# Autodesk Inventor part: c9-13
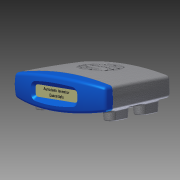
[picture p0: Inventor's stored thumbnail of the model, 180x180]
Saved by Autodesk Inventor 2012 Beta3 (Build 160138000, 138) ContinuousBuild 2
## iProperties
Created: 2010-12
Part Number: c9-13
Material: Default
Document SubType Name: Modeling
Designer: Beta-8540w
Density: 1 g/cm^3
Author: Beta-8540w
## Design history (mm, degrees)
sketch "Sketch1"
  geometry: L1 (-60, -12)-(60, -12); L2 (60, -12)-(60, 12); L3 (60, 12)-(-60, 12); L4 (-60, 12)-(-60, -12); A1 r 350 centre (0, -332.819) between (60, 12) and (-60, 12); A2 r 350 centre (0, 332.819) between (-60, -12) and (60, -12); 3 further points
  constraints: 8 end point, 4 point on circle, 2 centre point, 2 midpoint, 2 parallel, 1 equal radius, 1 horizontal, 1 horizontal alignment, 1 perpendicular, 1 vertical alignment
  dimensions: "d0" = 120 distance of L3.end L2.end; "d1" = 24 distance of L2.end L1.end; "d2" = 350 radius of A1
workplane "Work Plane4"
sketch "Sketch5"
  geometry: L1 (-60, 12)-(-60, -12) reference; L2 (60, -12)-(60, 12) reference; L3 (-58, 10.314)-(-58, -10.314); L4 (58, -10.314)-(58, 10.314); A1 r 350 centre (0, 332.819) between (-60, -12) and (60, -12) reference; A2 r 350 centre (0, -332.819) between (60, 12) and (-60, 12) reference; A3 r 348 centre (0, 332.819) between (-58, -10.314) and (58, -10.314); A4 r 348 centre (0, -332.819) between (58, 10.314) and (-58, 10.314); 1 further point
  constraints: 4 end point, 4 point on circle, 2 centre point, 3 other
  dimensions: "d37" = 2 distance between parallel lines of L2 L4
sketch "Sketch6"
  geometry: L1 (-60, 0)-(60, 0); L2 (60, 0)-(58.843, 22.085); L3 (-60, 0)-(-58.779, 23.307); A1 r 691.758 centre (630.81, -36.204) between (-60, 0) and (-58, -100); A2 r 691.758 centre (-630.81, -36.204) between (58, -100) and (60, 0); 1 further point
  constraints: 6 end point, 4 point on circle, 2 centre point, 2 tangent, 1 horizontal
  dimensions: "d53" = 87 deg angle of L1 L3; "d54" = 87 deg angle of L1 L2 (= d53)
sketch "Sketch7"
  geometry: L1 (17.181, 0)-(12, 0) reference; L2 (15.181, -100)-(10.314, -100) reference; L3 (17.181, 0)-(16.768, 11.838); A1 r 911.322 centre (-893.585, -31.805) between (15.181, -100) and (17.181, 0); 1 further point
  constraints: 2 end point, 2 point on circle, 1 centre point, 1 tangent
  dimensions: "d56" = 88 deg angle of L1 L3
feature "LoftSrf2" sketch "Sketch5", "Sketch6", "Sketch7" dims "d57" = 0, "d58" = 90 deg, "d59" = 0, "d60" = 90 deg, "d61" = 0, "d62" = 90 deg, "d63" = 0, "d64" = 90 deg, "d65" = 0, "d66" = 90 deg
sketch "Sketch2"
  geometry: L1 (-75, -16)-(75, -16); L2 (-75, -60)-(75, -60); A1 r 183.781 centre (0, -183.781) between (75, -16) and (-75, -16); 2 further points
  constraints: 4 end point, 3 point on circle, 1 centre point, 1 coincident, 1 horizontal, 1 parallel
  dimensions: "d5" = 16 distance from line of point (0, 0) L1; "d7" = 60 distance from line of point (0, 0) L2; "d55" = 150 distance of L1.start L1.end
feature "RevolutionSrf1" sketch "Sketch2" dims angle "d8" = 40 deg
patch "Boundary Patch1" dims "d13" = 0, "d67" = 0, "d68" = 0, "d69" = 0, "d70" = 0
workplane "Work Plane1"
sketch "Sketch3"
  geometry: L1 (52, -85)-(52, -73); L2 (38, -73)-(38, -85); A1 r 7 centre (45, -73) between (52, -73) and (38, -73); A2 r 7 centre (45, -85) between (38, -85) and (52, -85); 1 further point
  constraints: 4 end point, 4 point on circle, 4 tangent, 2 centre point, 1 parallel, 1 vertical
  dimensions: "d15" = 12 distance of L1.start L1.end; "d16" = 7 radius of A1; "d50" = 45 horizontal distance of A1.centre point (0, 0); "d51" = 85 vertical distance of point (0, 0) A2.centre
extrude_surface "ExtrusionSrf2" sketch "Sketch3" dims "d19" = 14, "d20" = 5 deg
pattern_linear "Rectangular Pattern1" dims "d23" = 90
workplane "Work Plane2"
feature "Sculpt1"
sketch "Sketch4"
  geometry: L1 (-24.5, 6)-(24.5, 6); L2 (27.5, 3)-(27.5, -3); L3 (24.5, -6)-(-24.5, -6); L4 (-27.5, -3)-(-27.5, 3); A1 r 3 centre (-24.5, 3) between (-24.5, 6) and (-27.5, 3); A2 r 3 centre (24.5, 3) between (27.5, 3) and (24.5, 6); A3 r 3 centre (24.5, -3) between (24.5, -6) and (27.5, -3); A4 r 3 centre (-24.5, -3) between (-27.5, -3) and (-24.5, -6); 6 further points
  constraints: 8 end point, 8 point on circle, 8 tangent, 6 point on line, 4 centre point, 3 equal radius, 2 midpoint, 2 parallel, 1 horizontal, 1 horizontal alignment, 1 perpendicular, 1 vertical alignment
  dimensions: "d28" = 55 distance of point (27.5, -6) point (-27.5, -6); "d29" = 12 distance of point (27.5, 6) point (27.5, -6); "d30" = 3 radius of A1
extrude_surface "ExtrusionSrf6" sketch "Sketch4" dims "d31" = 14, "d32" = 45 deg
patch "Boundary Patch2" dims "d33" = 0, "d34" = 0
fillet "Fillet1" dims "d79" = 4, "d80" = 3, "d81" = 1
feature "Sculpt2"
node "Splitting Plane 1"
shell "Shell1" dims "d83" = 2
split "Split1"
  body "Solid1"
feature "Lip1" dims "d188" = 1, "d189" = 1, "d190" = 0, "d191" = 0, "d192" = 0, "d193" = 0
feature "Lip2" dims "d194" = 1, "d195" = 1, "d196" = 0, "d197" = 0, "d198" = 0, "d199" = 0.5
split "Split3"
  node "Back"
sketch "Sketch9"
  geometry: L1 (50.167, -73)-(50.167, -85) reference; L2 (39.833, -85)-(39.833, -73) reference; L3 (45, -73)-(45, -85); L4 (45, -85)-(39.833, -85); A1 r 5.167 centre (45, -73) between (50.167, -73) and (39.833, -73) reference; A2 r 5.167 centre (45, -85) between (39.833, -85) and (50.167, -85) reference; 5 further points
  constraints: 4 end point, 1 horizontal, 1 midpoint, 1 parallel, 1 perpendicular, 1 vertical, 3 other
  dimensions: "d86" = 90 distance of point (45, -79) point (-45, -79); "d89" = 40 distance of point (45, -79) point (45, -39)
  node "Projected Loop1"
feature "Boss1" dims "d92" = 0, "d93" = 0, "d94" = 7, "d95" = 2, "d96" = 0.5, "d97" = 6, "d98" = 1.25, "d99" = 3.5, "d100" = 2.5 deg, "d101" = 2.5 deg, "d102" = 2.5 deg, "d103" = 2.5 deg, "d104" = 90 deg, "d107" = 2, "d108" = 2, "d109" = 10, "d110" = 0, "d111" = 10 deg, "d112" = 2.5 deg, "d113" = 0, "d114" = 0, "d115" = 0, "d116" = 360 deg
feature "Boss2" dims "d117" = 3, "d118" = 0, "d119" = 6, "d120" = 3, "d121" = 9.5, "d122" = 2 deg, "d123" = 1 deg, "d126" = 2, "d127" = 2, "d128" = 10, "d129" = 0, "d130" = 10 deg, "d131" = 2.5 deg, "d132" = 0, "d133" = 0, "d134" = 0, "d135" = 360 deg
workplane "Work Plane6"
sketch "Sketch10"
  geometry: L1 (24, -85)-(-24, -85); L2 (-30, -79)-(-30, -51); L3 (-24, -45)-(24, -45); L4 (30, -51)-(30, -79); L5 (54.344, -100)-(-54.344, -100) reference; A1 r 6 centre (-24, -51) between (-24, -45) and (-30, -51); A2 r 6 centre (24, -51) between (30, -51) and (24, -45); A3 r 6 centre (24, -79) between (24, -85) and (30, -79); A4 r 6 centre (-24, -79) between (-30, -79) and (-24, -85); 5 further points
  constraints: 8 end point, 8 point on circle, 8 tangent, 6 point on line, 4 centre point, 3 equal radius, 2 parallel, 1 horizontal, 1 midpoint, 1 perpendicular, 1 vertical alignment
  dimensions: "d137" = 60 distance of point (-30, -45) point (30, -45); "d138" = 40 distance of point (-30, -85) point (-30, -45); "d139" = 15 distance between parallel lines of L5 L1; "d141" = 6 radius of A2
feature "Rest1" sketch "Sketch10" dims "d142" = 5, "d143" = 0, "d144" = 0, "d145" = 0, "d146" = 2 deg, "d147" = 2 deg, "d148" = 2
feature "Rule Fillet1" dims "d149" = 2, "d150" = 1
workplane "Work Plane7"
sketch "Sketch11" dims "d154" = 16, "d155" = 8, "d161" = 10, "d168" = 10
  geometry: L1 (-13, -39.858)-(-13, -90.142); L2 (-25.187, -85)-(29.449, -85); L3 (0, -39.858)-(0, -90.142); L4 (13, -39.858)-(13, -90.142); L5 (-25.187, -77)-(29.449, -77); L6 (-25.187, -69)-(29.449, -69); L7 (-25.187, -61)-(29.449, -61); L8 (-25.187, -53)-(29.449, -53); L9 (-25.187, -45)-(29.449, -45); C1 r 22.5 at (0, -65); 3 further points; 1 other entity
  constraints: 18 end point, 2 coincident, 2 vertical, 1 centre point, 1 horizontal, 1 midpoint, 1 perpendicular, 1 vertical alignment, 23 other
  dimensions: "d152" = 45 diameter of C1; "d153" = 65 distance of point (0, 0) C1.centre; "d158" = 13 distance of L1.start L3.start; "d165" = 8 distance of L2.start L5.start; "d170" = 4 distance from line of L7 point (0, -65)
feature "Grill1" sketch "Sketch11" dims "d173" = 2, "d174" = 0, "d175" = 1, "d176" = 2, "d177" = 0, "d178" = 1, "d179" = 0.5, "d180" = 0, "d181" = 2, "d182" = 1, "d183" = 2 deg, "d184" = 0, "d185" = 88.84492
sketch "Sketch12"
  geometry: L1 (-12.481, -61.203)-(12.401, -61.203); L2 (12.401, -61.203)-(12.401, -68.714); L3 (12.401, -68.714)-(-12.481, -68.714); L4 (-12.481, -68.714)-(-12.481, -61.203); 1 further point
  constraints: 2 other
emboss "Emboss1" sketch "Sketch12" dims "d186" = 0.5, "d187" = 0
sketch "Sketch13"
  geometry: L1 (0, 15.66)-(0, -14.781); 6 further points
  constraints: 2 end point, 1 coincident, 1 point on line, 1 vertical, 4 other
feature "Snap Fit1" sketch "Sketch13" dims "d200" = 4, "d201" = 2.5, "d202" = 1, "d203" = 0.9, "d204" = 10.2, "d205" = 10, "d206" = 1, "d207" = 1, "d208" = 50 deg, "d209" = 50 deg
fillet "Fillet2" dims "d213" = 2
workplane "Work Plane8"
sketch "Sketch14"
  geometry: L1 (-8.644, -6.828)-(57.644, -6.828); L2 (6.5, 3.689)-(6.5, -17.346); L3 (24.5, 3.689)-(24.5, -17.346); L4 (42.5, 3.689)-(42.5, -17.346); 2 further points
  constraints: 8 end point, 4 parallel, 2 horizontal alignment, 2 midpoint, 1 coincident, 1 horizontal, 1 perpendicular
  dimensions: "d211" = 18 distance between parallel lines of L3 L2; "d212" = 18 distance between parallel lines of L4 L3 (= d211)
feature "Rib1" sketch "Sketch14" dims "d214" = 2, "d215" = 1, "d216" = 5 deg, "d217" = 0, "d218" = 1, "d219" = 1
sketch "Sketch15"
  geometry: L1 (-30, 10)-(30, 10); L2 (30, 10)-(30, -10); L3 (30, -10)-(-30, -10); L4 (-30, -10)-(-30, 10); 3 further points; 1 other entity
  constraints: 2 midpoint, 1 horizontal alignment, 1 vertical alignment, 2 other
  dimensions: "d221" = 60 distance of L1.start L1.end
feature "Decal1" sketch "Sketch15"
body "Srf2"
body "Srf3"
body "Srf4"
body "Srf5"
body "Srf6"
body "Srf7"
body "Srf8"
body "Srf9"
body "Srf11"
feature "Stitch Surface1"
body "Srf12"
node "Image1"
extrude_surface "ExtrusionSrf3"
extrude_surface "ExtrusionSrf4"
extrude_surface "ExtrusionSrf5"
node "Front"
node "Back - Top"
node "Back - Bottom"
other parameters: "d14" = -24, "d52" = -6, "d171" = 1, "d172" = 2, "d210" = -1
